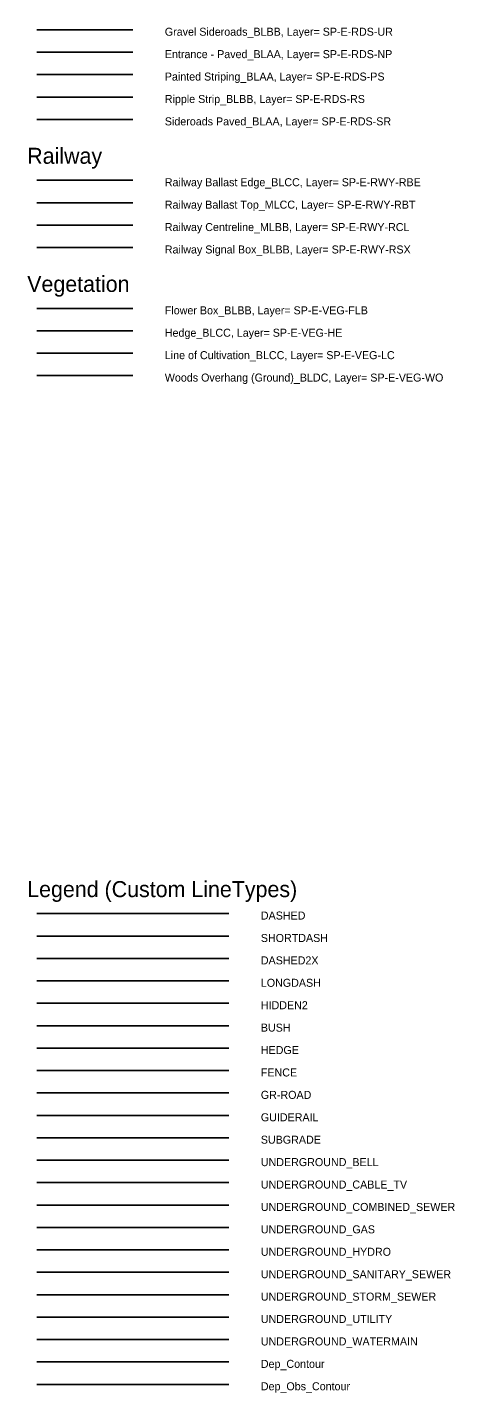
# Model space of a CAD drawing. Extents: x 500528 to 502626, y 4210261 to 4212624.
# Drawn here: x 501883.6 to 502017.1, y 4211605 to 4212031.4 of the extents above; entities that cross this region are included whole.
import ezdxf

# ---------------------------------------------------------------- set-up
doc = ezdxf.new("R2010")
doc.units = 0
for name, color, linetype in [('Default', 7, 'Continuous'), ('SP-E-BAR-FN', 7, 'Continuous'), ('SP-E-BAR-GU', 7, 'Continuous'), ('SP-E-BDY-CITY', 7, 'Continuous'), ('SP-E-CTR-MINR-DEPO', 7, 'Continuous'), ('SP-E-CTR-MINR-DEPR', 7, 'Continuous'), ('SP-E-DRN-BD', 7, 'Continuous'), ('SP-E-DRN-EWL', 7, 'Continuous'), ('SP-E-DRN-SAN', 7, 'Continuous'), ('SP-E-DRN-SEW', 7, 'Continuous'), ('SP-E-DRN-SEWC', 7, 'Continuous'), ('SP-E-GND-EC', 7, 'Continuous'), ('SP-E-RDS-NG', 7, 'Continuous'), ('SP-E-RDS-NP', 7, 'Continuous'), ('SP-E-RDS-PS', 7, 'Continuous'), ('SP-E-RDS-RS', 7, 'Continuous'), ('SP-E-RDS-SR', 7, 'Continuous'), ('SP-E-RDS-UR', 7, 'Continuous'), ('SP-E-RWY-RBE', 7, 'Continuous'), ('SP-E-RWY-RBT', 7, 'Continuous'), ('SP-E-RWY-RCL', 7, 'Continuous'), ('SP-E-RWY-RSX', 7, 'Continuous'), ('SP-E-UTL-UB', 7, 'Continuous'), ('SP-E-UTL-UG', 7, 'Continuous'), ('SP-E-UTL-UH', 7, 'Continuous'), ('SP-E-UTL-UT', 7, 'Continuous'), ('SP-E-UTL-UTV', 7, 'Continuous'), ('SP-E-UTL-UW', 7, 'Continuous'), ('SP-E-VEG-FLB', 7, 'Continuous'), ('SP-E-VEG-HE', 7, 'Continuous'), ('SP-E-VEG-LC', 7, 'Continuous'), ('SP-E-VEG-VEGE', 7, 'Continuous'), ('SP-E-VEG-WD', 7, 'Continuous'), ('SP-E-VEG-WO', 7, 'Continuous')]:
    doc.layers.add(name, color=color, linetype=linetype)

msp = doc.modelspace()

# ---------------------------------------------------------------- linework, layer by layer
at = {"layer": 'SP-E-BAR-FN'}
msp.add_line((501886.55, 4211705.59), (501946.55, 4211705.59), dxfattribs=at)
at = {"layer": 'SP-E-BAR-GU'}
msp.add_line((501886.55, 4211691.59), (501946.55, 4211691.59), dxfattribs=at)
at = {"layer": 'SP-E-BDY-CITY'}
msp.add_line((501886.55, 4211684.59), (501946.55, 4211684.59), dxfattribs=at)
at = {"layer": 'SP-E-CTR-MINR-DEPO'}
msp.add_line((501886.55, 4211607.59), (501946.55, 4211607.59), dxfattribs=at)
at = {"layer": 'SP-E-CTR-MINR-DEPR'}
msp.add_line((501886.55, 4211614.59), (501946.55, 4211614.59), dxfattribs=at)
at = {"layer": 'SP-E-DRN-BD'}
msp.add_line((501886.55, 4211740.59), (501946.55, 4211740.59), dxfattribs=at)
at = {"layer": 'SP-E-DRN-EWL'}
msp.add_line((501886.55, 4211747.59), (501946.55, 4211747.59), dxfattribs=at)
at = {"layer": 'SP-E-DRN-SAN'}
msp.add_line((501886.55, 4211642.59), (501946.55, 4211642.59), dxfattribs=at)
at = {"layer": 'SP-E-DRN-SEW'}
msp.add_line((501886.55, 4211635.59), (501946.55, 4211635.59), dxfattribs=at)
at = {"layer": 'SP-E-DRN-SEWC'}
msp.add_line((501886.55, 4211663.59), (501946.55, 4211663.59), dxfattribs=at)
at = {"layer": 'SP-E-GND-EC'}
msp.add_line((501886.55, 4211733.59), (501946.55, 4211733.59), dxfattribs=at)
at = {"layer": 'SP-E-RDS-NG'}
msp.add_line((501886.55, 4211726.59), (501946.55, 4211726.59), dxfattribs=at)
at = {"layer": 'SP-E-RDS-NP'}
msp.add_line((501886.55, 4212023.59), (501916.55, 4212023.59), dxfattribs=at)
at = {"layer": 'SP-E-RDS-PS'}
msp.add_line((501886.55, 4212016.59), (501916.55, 4212016.59), dxfattribs=at)
at = {"layer": 'SP-E-RDS-RS'}
msp.add_line((501886.55, 4212009.59), (501916.55, 4212009.59), dxfattribs=at)
at = {"layer": 'SP-E-RDS-SR'}
msp.add_line((501886.55, 4212002.59), (501916.55, 4212002.59), dxfattribs=at)
at = {"layer": 'SP-E-RDS-UR'}
for p, q in [((501886.55, 4212030.59), (501916.55, 4212030.59)), ((501886.55, 4211698.59), (501946.55, 4211698.59))]:
    msp.add_line(p, q, dxfattribs=at)
at = {"layer": 'SP-E-RWY-RBE'}
msp.add_line((501886.55, 4211983.59), (501916.55, 4211983.59), dxfattribs=at)
at = {"layer": 'SP-E-RWY-RBT'}
msp.add_line((501886.55, 4211976.59), (501916.55, 4211976.59), dxfattribs=at)
at = {"layer": 'SP-E-RWY-RCL'}
msp.add_line((501886.55, 4211969.59), (501916.55, 4211969.59), dxfattribs=at)
at = {"layer": 'SP-E-RWY-RSX'}
msp.add_line((501886.55, 4211962.59), (501916.55, 4211962.59), dxfattribs=at)
at = {"layer": 'SP-E-UTL-UB'}
msp.add_line((501886.55, 4211677.59), (501946.55, 4211677.59), dxfattribs=at)
at = {"layer": 'SP-E-UTL-UG'}
msp.add_line((501886.55, 4211656.59), (501946.55, 4211656.59), dxfattribs=at)
at = {"layer": 'SP-E-UTL-UH'}
msp.add_line((501886.55, 4211649.59), (501946.55, 4211649.59), dxfattribs=at)
at = {"layer": 'SP-E-UTL-UT'}
msp.add_line((501886.55, 4211628.59), (501946.55, 4211628.59), dxfattribs=at)
at = {"layer": 'SP-E-UTL-UTV'}
msp.add_line((501886.55, 4211670.59), (501946.55, 4211670.59), dxfattribs=at)
at = {"layer": 'SP-E-UTL-UW'}
msp.add_line((501886.55, 4211621.59), (501946.55, 4211621.59), dxfattribs=at)
at = {"layer": 'SP-E-VEG-FLB'}
msp.add_line((501886.55, 4211943.59), (501916.55, 4211943.59), dxfattribs=at)
at = {"layer": 'SP-E-VEG-HE'}
for p, q in [((501886.55, 4211936.59), (501916.55, 4211936.59)), ((501886.55, 4211712.59), (501946.55, 4211712.59))]:
    msp.add_line(p, q, dxfattribs=at)
at = {"layer": 'SP-E-VEG-LC'}
msp.add_line((501886.55, 4211929.59), (501916.55, 4211929.59), dxfattribs=at)
at = {"layer": 'SP-E-VEG-VEGE'}
msp.add_line((501886.55, 4211754.59), (501946.55, 4211754.59), dxfattribs=at)
at = {"layer": 'SP-E-VEG-WD'}
msp.add_line((501886.55, 4211719.59), (501946.55, 4211719.59), dxfattribs=at)
at = {"layer": 'SP-E-VEG-WO'}
msp.add_line((501886.55, 4211922.59), (501916.55, 4211922.59), dxfattribs=at)

# ---------------------------------------------------------------- texts
at = {"layer": 'Default'}
for s, p in [('Railway ', (501883.55, 4211988.74)), ('Vegetation ', (501883.55, 4211948.74)), ('Legend (Custom LineTypes) ', (501883.55, 4211759.74))]:
    msp.add_text(s, height=5, dxfattribs=at).set_placement(p)
at = {"layer": 'SP-E-BAR-FN'}
msp.add_text('FENCE ', height=2.5, dxfattribs=at).set_placement((501956.55, 4211703.74))
at = {"layer": 'SP-E-BAR-GU'}
msp.add_text('GUIDERAIL ', height=2.5, dxfattribs=at).set_placement((501956.55, 4211689.74))
at = {"layer": 'SP-E-BDY-CITY'}
msp.add_text('SUBGRADE ', height=2.5, dxfattribs=at).set_placement((501956.55, 4211682.74))
at = {"layer": 'SP-E-CTR-MINR-DEPO'}
msp.add_text('Dep_Obs_Contour ', height=2.5, dxfattribs=at).set_placement((501956.55, 4211605.74))
at = {"layer": 'SP-E-CTR-MINR-DEPR'}
msp.add_text('Dep_Contour ', height=2.5, dxfattribs=at).set_placement((501956.55, 4211612.74))
at = {"layer": 'SP-E-DRN-BD'}
msp.add_text('DASHED2X ', height=2.5, dxfattribs=at).set_placement((501956.55, 4211738.74))
at = {"layer": 'SP-E-DRN-EWL'}
msp.add_text('SHORTDASH ', height=2.5, dxfattribs=at).set_placement((501956.55, 4211745.74))
at = {"layer": 'SP-E-DRN-SAN'}
msp.add_text('UNDERGROUND_SANITARY_SEWER ', height=2.5, dxfattribs=at).set_placement((501956.55, 4211640.74))
at = {"layer": 'SP-E-DRN-SEW'}
msp.add_text('UNDERGROUND_STORM_SEWER ', height=2.5, dxfattribs=at).set_placement((501956.55, 4211633.74))
at = {"layer": 'SP-E-DRN-SEWC'}
msp.add_text('UNDERGROUND_COMBINED_SEWER ', height=2.5, dxfattribs=at).set_placement((501956.55, 4211661.74))
at = {"layer": 'SP-E-GND-EC'}
msp.add_text('LONGDASH ', height=2.5, dxfattribs=at).set_placement((501956.55, 4211731.74))
at = {"layer": 'SP-E-RDS-NG'}
msp.add_text('HIDDEN2 ', height=2.5, dxfattribs=at).set_placement((501956.55, 4211724.74))
at = {"layer": 'SP-E-RDS-NP'}
msp.add_text('Entrance - Paved_BLAA, Layer= SP-E-RDS-NP ', height=2.5, dxfattribs=at).set_placement((501926.55, 4212021.74))
at = {"layer": 'SP-E-RDS-PS'}
msp.add_text('Painted Striping_BLAA, Layer= SP-E-RDS-PS ', height=2.5, dxfattribs=at).set_placement((501926.55, 4212014.74))
at = {"layer": 'SP-E-RDS-RS'}
msp.add_text('Ripple Strip_BLBB, Layer= SP-E-RDS-RS ', height=2.5, dxfattribs=at).set_placement((501926.55, 4212007.74))
at = {"layer": 'SP-E-RDS-SR'}
msp.add_text('Sideroads Paved_BLAA, Layer= SP-E-RDS-SR ', height=2.5, dxfattribs=at).set_placement((501926.55, 4212000.74))
at = {"layer": 'SP-E-RDS-UR'}
for s, p in [('Gravel Sideroads_BLBB, Layer= SP-E-RDS-UR ', (501926.55, 4212028.74)), ('GR-ROAD ', (501956.55, 4211696.74))]:
    msp.add_text(s, height=2.5, dxfattribs=at).set_placement(p)
at = {"layer": 'SP-E-RWY-RBE'}
msp.add_text('Railway Ballast Edge_BLCC, Layer= SP-E-RWY-RBE ', height=2.5, dxfattribs=at).set_placement((501926.55, 4211981.74))
at = {"layer": 'SP-E-RWY-RBT'}
msp.add_text('Railway Ballast Top_MLCC, Layer= SP-E-RWY-RBT ', height=2.5, dxfattribs=at).set_placement((501926.55, 4211974.74))
at = {"layer": 'SP-E-RWY-RCL'}
msp.add_text('Railway Centreline_MLBB, Layer= SP-E-RWY-RCL ', height=2.5, dxfattribs=at).set_placement((501926.55, 4211967.74))
at = {"layer": 'SP-E-RWY-RSX'}
msp.add_text('Railway Signal Box_BLBB, Layer= SP-E-RWY-RSX ', height=2.5, dxfattribs=at).set_placement((501926.55, 4211960.74))
at = {"layer": 'SP-E-UTL-UB'}
msp.add_text('UNDERGROUND_BELL ', height=2.5, dxfattribs=at).set_placement((501956.55, 4211675.74))
at = {"layer": 'SP-E-UTL-UG'}
msp.add_text('UNDERGROUND_GAS ', height=2.5, dxfattribs=at).set_placement((501956.55, 4211654.74))
at = {"layer": 'SP-E-UTL-UH'}
msp.add_text('UNDERGROUND_HYDRO ', height=2.5, dxfattribs=at).set_placement((501956.55, 4211647.74))
at = {"layer": 'SP-E-UTL-UT'}
msp.add_text('UNDERGROUND_UTILITY ', height=2.5, dxfattribs=at).set_placement((501956.55, 4211626.74))
at = {"layer": 'SP-E-UTL-UTV'}
msp.add_text('UNDERGROUND_CABLE_TV ', height=2.5, dxfattribs=at).set_placement((501956.55, 4211668.74))
at = {"layer": 'SP-E-UTL-UW'}
msp.add_text('UNDERGROUND_WATERMAIN ', height=2.5, dxfattribs=at).set_placement((501956.55, 4211619.74))
at = {"layer": 'SP-E-VEG-FLB'}
msp.add_text('Flower Box_BLBB, Layer= SP-E-VEG-FLB ', height=2.5, dxfattribs=at).set_placement((501926.55, 4211941.74))
at = {"layer": 'SP-E-VEG-HE'}
for s, p in [('Hedge_BLCC, Layer= SP-E-VEG-HE ', (501926.55, 4211934.74)), ('HEDGE ', (501956.55, 4211710.74))]:
    msp.add_text(s, height=2.5, dxfattribs=at).set_placement(p)
at = {"layer": 'SP-E-VEG-LC'}
msp.add_text('Line of Cultivation_BLCC, Layer= SP-E-VEG-LC ', height=2.5, dxfattribs=at).set_placement((501926.55, 4211927.74))
at = {"layer": 'SP-E-VEG-VEGE'}
msp.add_text('DASHED ', height=2.5, dxfattribs=at).set_placement((501956.55, 4211752.74))
at = {"layer": 'SP-E-VEG-WD'}
msp.add_text('BUSH ', height=2.5, dxfattribs=at).set_placement((501956.55, 4211717.74))
at = {"layer": 'SP-E-VEG-WO'}
msp.add_text('Woods Overhang (Ground)_BLDC, Layer= SP-E-VEG-WO ', height=2.5, dxfattribs=at).set_placement((501926.55, 4211920.74))

doc.saveas('drawing.dxf')
